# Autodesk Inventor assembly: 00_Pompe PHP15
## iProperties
Shininess: 60.0
Length Units: 11269
Angle Units: 11279
Time Units: 11290
Mass Units: 11283
Length Display Precision: 3
Angle Display Precision: 2
Created: 2000-10
Part Number: 00_Pompe PHP15
Document SubType Name: Assemblage
Density: 0.0
Volumn: 0.0
Area: 0.0
PropertySet Name: Model Information
Control State: 0
Master: False
Checked Out: False
Author: Laurent GAUTHERON
